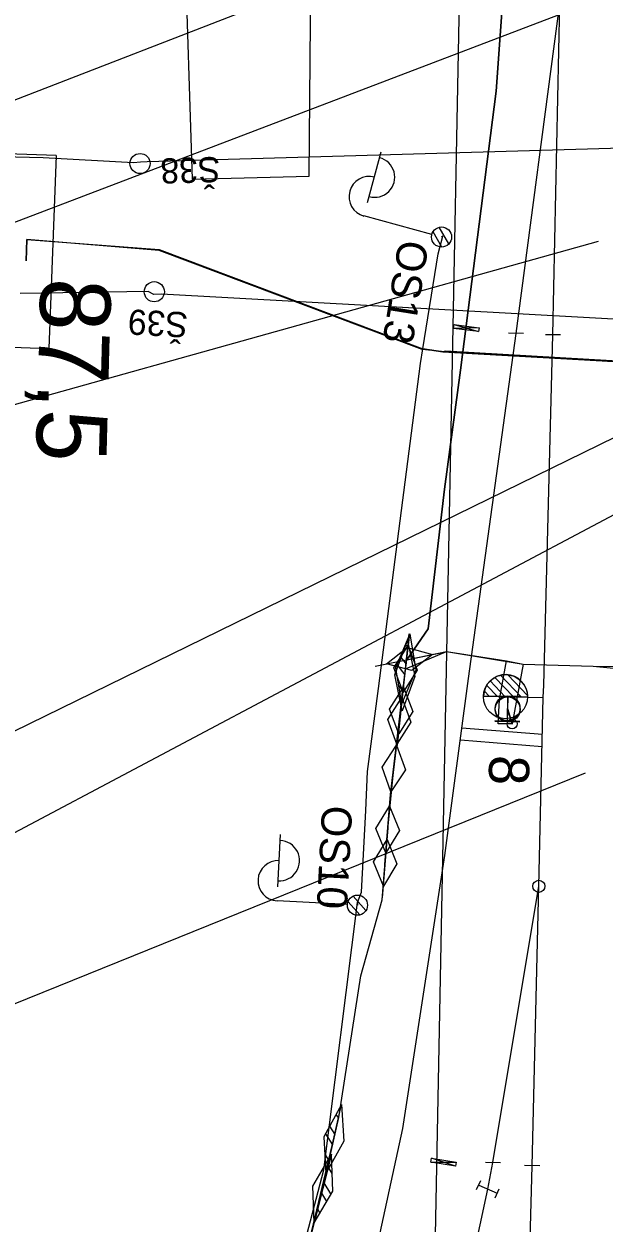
# Model space of a CAD drawing. Extents: x -545736 to -544888, y -1122892 to -1119128.
# Drawn here: x -545156.5 to -545127.7, y -1122462.5 to -1122403 of the extents above; entities that cross this region are included whole.
import ezdxf

# ---------------------------------------------------------------- set-up
doc = ezdxf.new("R2010")
doc.units = 0
for name, color, linetype in [('osvětlené plochy-hodnota-obrys', 7, 'Continuous'), ('Vrstva 1', 7, 'Continuous'), ('Vrstva 16', 7, 'Continuous'), ('Vrstva 16_plochy', 7, 'Continuous'), ('Vrstva 19 - Staniceni', 7, 'Continuous'), ('Vrstva 2', 7, 'Continuous'), ('Vrstva 25', 7, 'Continuous'), ('Vrstva 26', 7, 'Continuous'), ('Vrstva 27', 7, 'Continuous'), ('Vrstva 28 - zabzar', 7, 'Continuous'), ('Vrstva 3', 7, 'Continuous'), ('Vrstva 3 - Lisy - Pocitaci body', 7, 'Continuous'), ('Vrstva 31', 7, 'Continuous'), ('Vrstva 32', 7, 'Continuous'), ('Vrstva 33 - prvky sdelzar', 7, 'Continuous'), ('Vrstva 35', 7, 'Continuous'), ('Vrstva 43', 7, 'Continuous'), ('Vrstva 44', 7, 'Continuous'), ('Vrstva 63', 7, 'Continuous'), ('Vrstva 7', 7, 'Continuous'), ('Vrstva 7 - Namezniky-vystroj', 7, 'Continuous')]:
    doc.layers.add(name, color=color, linetype=linetype)

msp = doc.modelspace()

# ---------------------------------------------------------------- linework, layer by layer
at = {"layer": 'osvětlené plochy-hodnota-obrys'}
msp.add_lwpolyline([(-545134.488, -1122383.09), (-545138.436, -1122585.69), (-545142.696, -1122618.23), (-545150.566, -1122647.812), (-545144.37, -1122649.678)], dxfattribs=at)
at = {"layer": 'Vrstva 1'}
for p, q in [((-545132.029, -1122418.333), (-545129.856, -1122401.944)), ((-545133.18, -1122459.502), (-545130.897, -1122445.783))]:
    msp.add_line(p, q, dxfattribs=at)
for points in [[(-545130.199, -1122418.401), (-545129.856, -1122401.944), (-545129.646, -1122391.884)], [(-545145.86, -1122485.415), (-545140.531, -1122469.882), (-545139.118, -1122464.506), (-545137.664, -1122457.815), (-545135.575, -1122444.252), (-545134.387, -1122435.471), (-545132.029, -1122418.333)], [(-545130.678, -1122436.411), (-545130.656, -1122435.791), (-545130.199, -1122418.401)], [(-545131.231, -1122459.659), (-545130.897, -1122445.783), (-545130.678, -1122436.411)], [(-545143.381, -1122494.588), (-545139.286, -1122483.853), (-545137.099, -1122476.978), (-545136.326, -1122474.296), (-545133.431, -1122460.82), (-545133.18, -1122459.502)], [(-545132.113, -1122493.06), (-545131.69, -1122476.721), (-545131.231, -1122459.659)]]:
    msp.add_lwpolyline(points, dxfattribs=at)
at = {"layer": 'Vrstva 16'}
msp.add_lwpolyline([(-545148.504, -1122398.846), (-545148.13, -1122410.674), (-545142.311, -1122410.518), (-545142.214, -1122399.014)], close=True, dxfattribs=at)
at = {"layer": 'Vrstva 16_plochy'}
for points in [[(-545154.889, -1122409.491), (-545163.658, -1122409.205), (-545164.003, -1122418.764), (-545155.239, -1122419.077)], [(-545154.889, -1122409.491), (-545155.239, -1122419.077)]]:
    msp.add_lwpolyline(points, dxfattribs=at)
at = {"layer": 'Vrstva 2'}
for p, q in [((-545132.029, -1122418.333), (-545129.856, -1122401.944)), ((-545131.654, -1122418.341), (-545132.404, -1122418.325)), ((-545129.824, -1122418.398), (-545130.574, -1122418.404)), ((-545132.166, -1122436.378), (-545133.085, -1122435.414)), ((-545131.768, -1122436.387), (-545132.802, -1122435.303)), ((-545131.454, -1122436.31), (-545132.436, -1122435.279)), ((-545133.359, -1122436.349), (-545133.606, -1122436.09)), ((-545132.961, -1122436.358), (-545133.487, -1122435.807)), ((-545132.564, -1122436.368), (-545133.311, -1122435.584)), ((-545131.45, -1122436.395), (-545133.644, -1122436.342)), ((-545133.644, -1122436.342), (-545131.45, -1122436.394)), ((-545131.45, -1122436.394), (-545131.45, -1122436.395)), ((-545131.449, -1122436.395), (-545130.678, -1122436.411)), ((-545133.18, -1122459.502), (-545130.897, -1122445.783)), ((-545132.805, -1122459.511), (-545133.555, -1122459.493)), ((-545130.856, -1122459.669), (-545131.606, -1122459.649))]:
    msp.add_line(p, q, dxfattribs=at)
for points in [[(-545130.199, -1122418.401), (-545129.856, -1122401.944), (-545129.646, -1122391.884)], [(-545131.231, -1122459.659), (-545130.897, -1122445.783), (-545130.678, -1122436.411)]]:
    msp.add_lwpolyline(points, dxfattribs=at)
for centre, radius in [((-545132.553, -1122436.367), 1.097), ((-545130.897, -1122445.783), 0.3)]:
    msp.add_circle(centre, radius, dxfattribs=at)
msp.add_arc((-545132.547, -1122436.368), 1.098, 358.65694, 178.61779, dxfattribs=at)
at = {"layer": 'Vrstva 25'}
for p, q in [((-545139.41, -1122411.826), (-545138.732, -1122409.316)), ((-545136.214, -1122413.415), (-545139.592, -1122412.501)), ((-545135.715, -1122414.045), (-545136.153, -1122413.282)), ((-545135.371, -1122413.89), (-545135.848, -1122413.06)), ((-545143.869, -1122445.805), (-545143.73, -1122443.209)), ((-545140.411, -1122446.691), (-545143.906, -1122446.504)), ((-545139.792, -1122447.203), (-545140.38, -1122446.549)), ((-545139.488, -1122446.98), (-545140.128, -1122446.268))]:
    msp.add_line(p, q, dxfattribs=at)
for centre in [(-545135.731, -1122413.545), (-545135.731, -1122413.545), (-545139.912, -1122446.718), (-545139.912, -1122446.718)]:
    msp.add_circle(centre, 0.5, dxfattribs=at)
for centre, start, end in [((-545139.059, -1122410.574), 254.17506, 75.58021), ((-545139.332, -1122411.536), 74.87764, 254.87764), ((-545143.787, -1122444.508), 266.23421, 87.63936), ((-545143.853, -1122445.506), 86.93679, 266.93679)]:
    msp.add_arc(centre, 1, start, end, dxfattribs=at)
at = {"layer": 'Vrstva 26'}
for points in [[(-545134.594, -1122508.496), (-545134.254, -1122496.631), (-545133.939, -1122488.006), (-545137.081, -1122485.445), (-545147.387, -1122482.077), (-545141.585, -1122459.861), (-545139.907, -1122446.587), (-545139.716, -1122446.072), (-545139.499, -1122442.017), (-545139.407, -1122440.077), (-545138.864, -1122435.963), (-545136.776, -1122419.823), (-545136.659, -1122419.093), (-545135.901, -1122414.378), (-545135.664, -1122413.501), (-545135.731, -1122413.545)], [(-545113.588, -1122440.459), (-545114.2, -1122440.77), (-545115.03, -1122440.61), (-545114.46, -1122437.51), (-545112.75, -1122436.04), (-545114.11, -1122435.24), (-545111.34, -1122420.98), (-545110.467, -1122420.677), (-545135.537, -1122419.205), (-545135.677, -1122419.251), (-545136.659, -1122419.093)], [(-545139.907, -1122446.587), (-545139.912, -1122446.718)]]:
    msp.add_lwpolyline(points, dxfattribs=at)
at = {"layer": 'Vrstva 27'}
msp.add_line((-545132.227, -1122437.695), (-545132.233, -1122437.745), dxfattribs=at)
msp.add_line((-545132.227, -1122437.695), (-545132.233, -1122437.745), dxfattribs=at)
msp.add_circle((-545132.23, -1122437.72), 0.25, dxfattribs=at)
msp.add_circle((-545132.23, -1122437.72), 0.25, dxfattribs=at)
at = {"layer": 'Vrstva 28 - zabzar'}
for p, q in [((-545137.702, -1122436.726), (-545137.338, -1122433.254)), ((-545139.031, -1122434.846), (-545135.609, -1122434.154)), ((-545138.46, -1122434.731), (-545137.435, -1122433.93)), ((-545138.099, -1122434.929), (-545137.399, -1122433.833)), ((-545137.435, -1122433.93), (-545136.18, -1122434.269)), ((-545137.399, -1122433.833), (-545136.941, -1122435.051)), ((-545136.18, -1122434.269), (-545137.205, -1122435.07)), ((-545137.205, -1122435.07), (-545138.46, -1122434.731)), ((-545137.641, -1122436.147), (-545138.099, -1122434.929)), ((-545137.922, -1122438.786), (-545137.558, -1122435.314)), ((-545136.941, -1122435.051), (-545137.641, -1122436.147)), ((-545138.319, -1122436.989), (-545137.619, -1122435.893)), ((-545138.023, -1122439.305), (-545137.637, -1122435.835)), ((-545137.619, -1122435.893), (-545137.161, -1122437.111)), ((-545138.408, -1122437.506), (-545137.702, -1122436.414)), ((-545137.702, -1122436.414), (-545137.252, -1122437.634)), ((-545137.861, -1122438.207), (-545138.319, -1122436.989)), ((-545137.161, -1122437.111), (-545137.861, -1122438.207)), ((-545137.958, -1122438.726), (-545138.408, -1122437.506)), ((-545137.252, -1122437.634), (-545137.958, -1122438.726)), ((-545137.902, -1122438.197), (-545138.318, -1122441.663)), ((-545138.688, -1122439.861), (-545137.971, -1122438.775)), ((-545137.971, -1122438.775), (-545137.532, -1122439.999)), ((-545138.249, -1122441.085), (-545138.688, -1122439.861)), ((-545137.532, -1122439.999), (-545138.249, -1122441.085)), ((-545138.55, -1122444.7), (-545138.27, -1122441.22)), ((-545138.99, -1122442.913), (-545138.317, -1122441.8)), ((-545138.317, -1122441.8), (-545137.83, -1122443.007)), ((-545138.503, -1122444.12), (-545138.99, -1122442.913)), ((-545138.672, -1122446.36), (-545138.388, -1122442.88)), ((-545137.83, -1122443.007), (-545138.503, -1122444.12)), ((-545139.11, -1122444.573), (-545138.435, -1122443.46)), ((-545138.435, -1122443.46), (-545137.95, -1122444.667)), ((-545138.625, -1122445.78), (-545139.11, -1122444.573)), ((-545137.95, -1122444.667), (-545138.625, -1122445.78))]:
    msp.add_line(p, q, dxfattribs=at)
for points in [[(-545137.46, -1122434.53), (-545136.39, -1122433), (-545135.58, -1122426.07), (-545134.79, -1122420.15), (-545133.02, -1122406.31), (-545132.05, -1122392.7), (-545132.2, -1122385.52), (-545132.72, -1122373.87), (-545132.94, -1122371.34), (-545133.16, -1122368.81)], [(-545142.93, -1122466.01), (-545141.63, -1122460.79), (-545140.84, -1122457.27), (-545139.75, -1122450.22), (-545138.68, -1122446.46), (-545138.53, -1122444.62), (-545138.41, -1122442.96), (-545138.11, -1122439.93), (-545137.87, -1122437.93), (-545137.83, -1122437.57), (-545137.74, -1122437.05), (-545137.52, -1122434.99), (-545137.46, -1122434.53), (-545137.32, -1122434.5), (-545135.49, -1122434.13), (-545132.82, -1122434.54), (-545131.67, -1122434.76), (-545128.2, -1122434.85), (-545124.58, -1122434.9)], [(-545142.93, -1122466.01), (-545141.63, -1122460.79), (-545140.84, -1122457.27), (-545139.75, -1122450.22), (-545138.68, -1122446.46), (-545138.53, -1122444.62), (-545138.41, -1122442.96), (-545138.11, -1122439.93), (-545137.87, -1122437.93), (-545137.83, -1122437.57), (-545137.74, -1122437.05), (-545137.52, -1122434.99), (-545137.46, -1122434.53), (-545137.32, -1122434.5), (-545135.49, -1122434.13), (-545132.82, -1122434.54), (-545132.5, -1122434.59), (-545131.67, -1122434.76), (-545128.2, -1122434.85), (-545124.58, -1122434.9)], [(-545132.45, -1122436.95), (-545132.23, -1122437.72), (-545132.92, -1122437.71), (-545132.86, -1122436.51), (-545132.5, -1122434.59)], [(-545131.67, -1122434.76), (-545132.23, -1122437.72), (-545132.45, -1122436.95)]]:
    msp.add_lwpolyline(points, dxfattribs=at)
at = {"layer": 'Vrstva 3'}
for p, q in [((-545131.821, -1122436.394), (-545133.052, -1122436.365)), ((-545132.436, -1122436.379), (-545132.466, -1122437.611)), ((-545131.85, -1122437.625), (-545133.081, -1122437.596)), ((-545133.989, -1122460.844), (-545133.786, -1122460.388)), ((-545133.888, -1122460.616), (-545132.974, -1122461.024)), ((-545133.076, -1122461.252), (-545132.873, -1122460.796))]:
    msp.add_line(p, q, dxfattribs=at)
msp.add_circle((-545132.45, -1122436.997), 0.616, dxfattribs=at)
at = {"layer": 'Vrstva 3 - Lisy - Pocitaci body'}
for p, q in [((-545133.051, -1122436.32), (-545131.82, -1122436.349)), ((-545132.464, -1122437.566), (-545132.436, -1122436.334)), ((-545133.08, -1122437.551), (-545131.849, -1122437.58))]:
    msp.add_line(p, q, dxfattribs=at)
msp.add_circle((-545132.451, -1122436.948), 0.616, dxfattribs=at)
at = {"layer": 'Vrstva 31'}
for points in [[(-545129.58, -1122347.14), (-545128.92, -1122347.33), (-545127.93, -1122353.9), (-545127.07, -1122367.16), (-545126.8, -1122372.84), (-545126.95, -1122373.3), (-545128.47, -1122373.7), (-545131.38, -1122373.88), (-545132.72, -1122373.87), (-545132.2, -1122385.52), (-545132.05, -1122392.7), (-545133.02, -1122406.31), (-545134.79, -1122420.15), (-545135.58, -1122426.07), (-545136.39, -1122433), (-545137.46, -1122434.53)], [(-545099.24, -1122402.115), (-545098.313, -1122409.178), (-545097.663, -1122416.204), (-545097.274, -1122424.459), (-545098.365, -1122424.645), (-545100.628, -1122425.068), (-545101.138, -1122425.054), (-545109.701, -1122421.713), (-545110.467, -1122420.727), (-545135.568, -1122419.245), (-545136.694, -1122419.128), (-545149.766, -1122414.21), (-545156.339, -1122413.66), (-545156.372, -1122414.724)], [(-545137.56, -1122435.33), (-545137.52, -1122434.99), (-545137.46, -1122434.53), (-545137.32, -1122434.5), (-545135.49, -1122434.13), (-545132.82, -1122434.54), (-545131.67, -1122434.76), (-545128.2, -1122434.85), (-545124.58, -1122434.9), (-545123.28, -1122435.33), (-545115.13, -1122435.9), (-545113.17, -1122435.96), (-545111.79, -1122436.35), (-545107.25, -1122436.01), (-545103.45, -1122435.89), (-545098.21, -1122435.16), (-545098.87, -1122433.13), (-545100.24, -1122425.44), (-545102.2, -1122418.85), (-545103.21, -1122414.3), (-545103.69, -1122412.05)], [(-545156.372, -1122414.724), (-545156.339, -1122413.66), (-545149.766, -1122414.16), (-545149.766, -1122414.16), (-545136.659, -1122419.093), (-545135.677, -1122419.251), (-545110.467, -1122420.677), (-545100.891, -1122425.245), (-545098.365, -1122424.695), (-545097.239, -1122424.494)], [(-545137.697, -1122437.075), (-545138.058, -1122435.291), (-545137.423, -1122433.585), (-545137.062, -1122435.369), (-545137.697, -1122437.075)], [(-545137.697, -1122437.075), (-545138.058, -1122435.291), (-545137.423, -1122433.585), (-545137.062, -1122435.369), (-545137.697, -1122437.075)], [(-545142.93, -1122466.01), (-545140.84, -1122457.27), (-545139.75, -1122450.22), (-545138.68, -1122446.46), (-545138.27, -1122441.22), (-545138.11, -1122439.93), (-545137.74, -1122437.05), (-545137.56, -1122435.33), (-545137.46, -1122434.53), (-545137.32, -1122434.5), (-545135.49, -1122434.13), (-545132.82, -1122434.54), (-545131.67, -1122434.76), (-545128.2, -1122434.85), (-545124.58, -1122434.9), (-545123.28, -1122435.33), (-545119.31, -1122435.79), (-545115.13, -1122435.9), (-545113.17, -1122435.96), (-545111.79, -1122436.35), (-545107.25, -1122436.01), (-545103.45, -1122435.89), (-545098.21, -1122435.16)]]:
    msp.add_lwpolyline(points, dxfattribs=at)
at = {"layer": 'Vrstva 32'}
for p, q in [((-545137.362, -1122433.38), (-545137.333, -1122433.438)), ((-545137.536, -1122433.762), (-545137.394, -1122433.943)), ((-545137.951, -1122434.774), (-545137.555, -1122435.279)), ((-545137.793, -1122434.372), (-545137.492, -1122434.756)), ((-545137.891, -1122435.788), (-545137.652, -1122436.091)), ((-545137.761, -1122436.536), (-545137.713, -1122436.595)), ((-545140.771, -1122456.744), (-545140.748, -1122456.804)), ((-545140.983, -1122457.107), (-545140.859, -1122457.301)), ((-545141.497, -1122458.072), (-545141.154, -1122458.614)), ((-545141.299, -1122457.688), (-545141.038, -1122458.1)), ((-545141.54, -1122459.086), (-545141.333, -1122459.412)), ((-545141.199, -1122459.286), (-545141.239, -1122459.221)), ((-545141.486, -1122459.844), (-545141.444, -1122459.908)), ((-545141.163, -1122460.044), (-545141.362, -1122459.714)), ((-545141.436, -1122461.437), (-545141.687, -1122461.019)), ((-545141.229, -1122461.058), (-545141.56, -1122460.507)), ((-545141.766, -1122462.01), (-545141.885, -1122461.813)), ((-545141.986, -1122462.368), (-545142.008, -1122462.307))]:
    msp.add_line(p, q, dxfattribs=at)
for points in [[(-545137.309, -1122433.241), (-545138.025, -1122434.929), (-545137.731, -1122436.739)], [(-545140.704, -1122456.611), (-545141.587, -1122458.219), (-545141.476, -1122460.049)], [(-545142.056, -1122462.5), (-545141.136, -1122460.913), (-545141.204, -1122459.08)]]:
    msp.add_lwpolyline(points, close=True, dxfattribs=at)
for points in [[(-545137.309, -1122433.241), (-545137.015, -1122435.051), (-545137.731, -1122436.739)], [(-545142.93, -1122466.01), (-545140.84, -1122457.27), (-545139.75, -1122450.22), (-545138.68, -1122446.46), (-545138.27, -1122441.22), (-545137.52, -1122434.99), (-545137.46, -1122434.53), (-545135.49, -1122434.13), (-545132.82, -1122434.54), (-545132.5, -1122434.59), (-545131.67, -1122434.76), (-545128.2, -1122434.85), (-545124.58, -1122434.9)], [(-545138.27, -1122441.22), (-545137.52, -1122434.99), (-545135.49, -1122434.13), (-545131.67, -1122434.76), (-545128.2, -1122434.85), (-545123.28, -1122435.33)], [(-545137.26, -1122503.3), (-545136.84, -1122494.09), (-545136.54, -1122488.04), (-545137.2, -1122485.39), (-545142.33, -1122483.7), (-545147.19, -1122482.16), (-545147.31, -1122480.5), (-545145.39, -1122475.04), (-545142.93, -1122466.01), (-545142.89, -1122465.81), (-545141.63, -1122460.79), (-545141.09, -1122458.33), (-545140.84, -1122457.27), (-545139.75, -1122450.22), (-545138.68, -1122446.46), (-545138.27, -1122441.22)], [(-545140.704, -1122456.611), (-545140.593, -1122458.441), (-545141.476, -1122460.049)], [(-545142.056, -1122462.5), (-545142.124, -1122460.667), (-545141.204, -1122459.08)]]:
    msp.add_lwpolyline(points, dxfattribs=at)
at = {"layer": 'Vrstva 33 - prvky sdelzar'}
for points in [[(-545110.467, -1122420.727), (-545135.568, -1122419.245)], [(-545135.49, -1122434.13), (-545132.82, -1122434.54), (-545132.5, -1122434.59), (-545131.67, -1122434.76), (-545128.2, -1122434.85), (-545124.58, -1122434.9), (-545123.28, -1122435.33), (-545119.31, -1122435.79), (-545115.13, -1122435.9), (-545113.17, -1122435.96)]]:
    msp.add_lwpolyline(points, dxfattribs=at)
at = {"layer": 'Vrstva 35'}
for points in [[(-545135.49, -1122434.13), (-545132.82, -1122434.54), (-545131.67, -1122434.76), (-545128.2, -1122434.85), (-545124.58, -1122434.9)], [(-545135.49, -1122434.13), (-545132.82, -1122434.54), (-545132.5, -1122434.59)], [(-545132.5, -1122434.59), (-545131.67, -1122434.76), (-545128.2, -1122434.85), (-545124.58, -1122434.9)]]:
    msp.add_lwpolyline(points, dxfattribs=at)
at = {"layer": 'Vrstva 43'}
for centre in [(-545150.713, -1122409.896), (-545150.006, -1122416.261)]:
    msp.add_circle(centre, 0.5, dxfattribs=at)
at = {"layer": 'Vrstva 44'}
for points in [[(-545161.563, -1122409.448), (-545161.04, -1122409.449), (-545159.873, -1122409.474), (-545158.718, -1122409.518), (-545157.567, -1122409.551), (-545155.535, -1122409.595), (-545151.035, -1122409.842), (-545150.699, -1122409.811), (-545150.354, -1122409.803), (-545117.558, -1122408.854), (-545117.209, -1122408.632), (-545117.207, -1122408.356), (-545114.472, -1122375.479)], [(-545053.287, -1122633.279), (-545063.238, -1122586.146), (-545063.248, -1122585.919), (-545063.296, -1122585.762), (-545072.411, -1122534.849), (-545072.406, -1122534.601), (-545072.52, -1122534.494), (-545080.043, -1122501.027), (-545080.093, -1122500.849), (-545080.193, -1122500.397), (-545087.505, -1122464.21), (-545087.659, -1122463.509), (-545087.757, -1122463.363), (-545099.069, -1122419.052), (-545099.193, -1122418.695), (-545099.586, -1122418.621), (-545116.487, -1122418.299), (-545117.079, -1122418.156), (-545117.605, -1122418.155), (-545149.644, -1122416.388), (-545150.026, -1122416.395), (-545150.307, -1122416.258), (-545156.662, -1122416.357)]]:
    msp.add_lwpolyline(points, dxfattribs=at)
at = {"layer": 'Vrstva 63'}
for p, q in [((-545117.157, -1122391.345), (-545179.271, -1122415.379)), ((-545105.11, -1122393.061), (-545178.191, -1122420.898)), ((-545099.334, -1122412.581), (-545172.254, -1122451.231)), ((-545127.956, -1122413.772), (-545176.91, -1122427.443)), ((-545108.468, -1122414.355), (-545173.267, -1122446.057)), ((-545128.603, -1122440.164), (-545171.063, -1122457.317))]:
    msp.add_line(p, q, dxfattribs=at)
at = {"layer": 'Vrstva 7'}
for p, q in [((-545134.718, -1122437.918), (-545130.721, -1122438.235)), ((-545134.799, -1122438.514), (-545130.736, -1122438.836))]:
    msp.add_line(p, q, dxfattribs=at)
at = {"layer": 'Vrstva 7 - Namezniky-vystroj'}
for p, q in [((-545135.109, -1122417.882), (-545133.897, -1122418.244)), ((-545135.038, -1122459.679), (-545136.238, -1122459.277))]:
    msp.add_line(p, q, dxfattribs=at)
for points in [[(-545133.87, -1122418.046), (-545135.136, -1122418.08), (-545135.109, -1122417.882), (-545133.87, -1122418.046), (-545133.897, -1122418.244), (-545135.136, -1122418.08)], [(-545136.271, -1122459.474), (-545135.005, -1122459.482), (-545135.038, -1122459.679), (-545136.271, -1122459.474), (-545136.238, -1122459.277), (-545135.005, -1122459.482)]]:
    msp.add_lwpolyline(points, dxfattribs=at)

# ---------------------------------------------------------------- texts
at = {"layer": 'Vrstva 19 - Staniceni'}
msp.add_text('87,5', height=3.5, rotation=268.50503, dxfattribs=at).set_placement((-545155.647, -1122415.556))
at = {"layer": 'Vrstva 2'}
msp.add_text('8', height=2, rotation=268.59325, dxfattribs=at).set_placement((-545133.358, -1122439.253))
at = {"layer": 'Vrstva 25'}
for s, rotation, p in [('OS13', 260.86707, (-545137.848, -1122413.631)), ('OS10', 266.93679, (-545141.663, -1122441.747))]:
    msp.add_text(s, height=1.5, rotation=rotation, dxfattribs=at).set_placement(p)
at = {"layer": 'Vrstva 43'}
for s, rotation, p in [('Š38', 181.65747, (-545146.745, -1122409.562)), ('Š39', 176.84325, (-545148.305, -1122417.294))]:
    msp.add_text(s, height=1.25, rotation=rotation, dxfattribs=at).set_placement(p)

doc.saveas('drawing.dxf')
